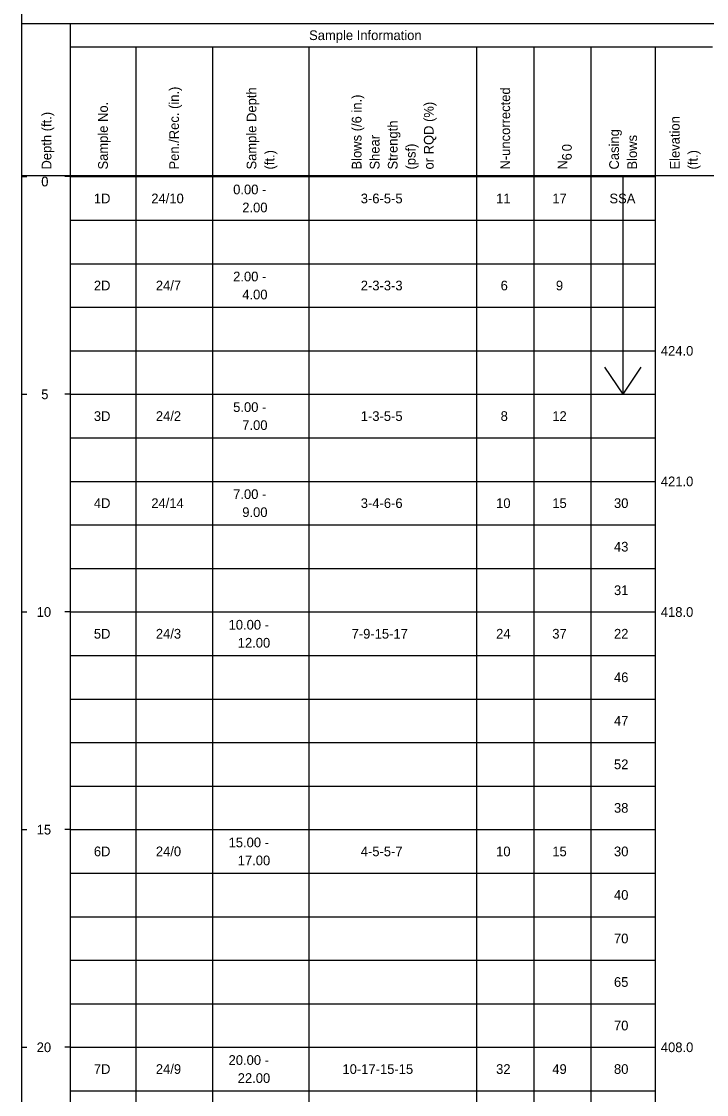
# Model space of a CAD drawing. Extents: x 9419 to 9552, y 6780 to 6865.
# Drawn here: x 9460.28 to 9476.01, y 6825.93 to 6850.58 of the extents above; entities that cross this region are included whole.
import ezdxf

# ---------------------------------------------------------------- set-up
doc = ezdxf.new("R2010")
doc.units = 0
doc.layers.add('7', color=7, linetype='Continuous')

msp = doc.modelspace()

# ---------------------------------------------------------------- linework, layer by layer
at = {"layer": '7'}
for q in [(9474.097, 6847.011), (9473.68, 6842.636), (9474.514, 6842.636)]:
    msp.add_line((9474.097, 6842.011), q, dxfattribs=at)
for points in [[(9460.282, 6860.114), (9460.282, 6821.983)], [(9460.282, 6850.528), (9491.778, 6850.528)], [(9461.4, 6850.528), (9461.4, 6821.983)], [(9461.4, 6849.992), (9476.148, 6849.992)], [(9462.909, 6849.992), (9462.909, 6821.983)], [(9464.665, 6849.992), (9464.665, 6821.983)], [(9466.879, 6849.992), (9466.879, 6821.983)], [(9470.734, 6849.992), (9470.734, 6821.983)], [(9472.046, 6849.992), (9472.046, 6821.983)], [(9473.359, 6849.992), (9473.359, 6821.983)], [(9474.835, 6849.992), (9474.835, 6821.983)], [(9460.282, 6847.038), (9491.778, 6847.038)], [(9460.282, 6847.011), (9460.404, 6847.011)], [(9461.4, 6847.011), (9461.279, 6847.011)], [(9461.4, 6847.011), (9462.909, 6847.011)], [(9462.909, 6847.011), (9464.665, 6847.011)], [(9464.665, 6847.011), (9466.879, 6847.011)], [(9466.879, 6847.011), (9470.734, 6847.011)], [(9470.734, 6847.011), (9472.046, 6847.011)], [(9472.046, 6847.011), (9473.359, 6847.011)], [(9473.359, 6847.011), (9474.835, 6847.011)], [(9461.4, 6846.011), (9462.909, 6846.011)], [(9462.909, 6846.011), (9464.665, 6846.011)], [(9464.665, 6846.011), (9466.879, 6846.011)], [(9466.879, 6846.011), (9470.734, 6846.011)], [(9470.734, 6846.011), (9472.046, 6846.011)], [(9472.046, 6846.011), (9473.359, 6846.011)], [(9473.359, 6846.011), (9474.835, 6846.011)], [(9461.4, 6845.011), (9462.909, 6845.011)], [(9462.909, 6845.011), (9464.665, 6845.011)], [(9464.665, 6845.011), (9466.879, 6845.011)], [(9466.879, 6845.011), (9470.734, 6845.011)], [(9470.734, 6845.011), (9472.046, 6845.011)], [(9472.046, 6845.011), (9473.359, 6845.011)], [(9473.359, 6845.011), (9474.835, 6845.011)], [(9461.4, 6844.011), (9462.909, 6844.011)], [(9462.909, 6844.011), (9464.665, 6844.011)], [(9464.665, 6844.011), (9466.879, 6844.011)], [(9466.879, 6844.011), (9470.734, 6844.011)], [(9470.734, 6844.011), (9472.046, 6844.011)], [(9472.046, 6844.011), (9473.359, 6844.011)], [(9473.359, 6844.011), (9474.835, 6844.011)], [(9461.4, 6843.011), (9462.909, 6843.011)], [(9462.909, 6843.011), (9464.665, 6843.011)], [(9464.665, 6843.011), (9466.879, 6843.011)], [(9466.879, 6843.011), (9470.734, 6843.011)], [(9470.734, 6843.011), (9472.046, 6843.011)], [(9472.046, 6843.011), (9473.359, 6843.011)], [(9473.359, 6843.011), (9474.835, 6843.011)], [(9460.282, 6842.011), (9460.404, 6842.011)], [(9461.4, 6842.011), (9461.279, 6842.011)], [(9461.4, 6842.011), (9462.909, 6842.011)], [(9462.909, 6842.011), (9464.665, 6842.011)], [(9464.665, 6842.011), (9466.879, 6842.011)], [(9466.879, 6842.011), (9470.734, 6842.011)], [(9470.734, 6842.011), (9472.046, 6842.011)], [(9472.046, 6842.011), (9473.359, 6842.011)], [(9473.359, 6842.011), (9474.835, 6842.011)], [(9461.4, 6841.011), (9462.909, 6841.011)], [(9462.909, 6841.011), (9464.665, 6841.011)], [(9464.665, 6841.011), (9466.879, 6841.011)], [(9466.879, 6841.011), (9470.734, 6841.011)], [(9470.734, 6841.011), (9472.046, 6841.011)], [(9472.046, 6841.011), (9473.359, 6841.011)], [(9473.359, 6841.011), (9474.835, 6841.011)], [(9461.4, 6840.011), (9462.909, 6840.011)], [(9462.909, 6840.011), (9464.665, 6840.011)], [(9464.665, 6840.011), (9466.879, 6840.011)], [(9466.879, 6840.011), (9470.734, 6840.011)], [(9470.734, 6840.011), (9472.046, 6840.011)], [(9472.046, 6840.011), (9473.359, 6840.011)], [(9473.359, 6840.011), (9474.835, 6840.011)], [(9461.4, 6839.011), (9462.909, 6839.011)], [(9462.909, 6839.011), (9464.665, 6839.011)], [(9464.665, 6839.011), (9466.879, 6839.011)], [(9466.879, 6839.011), (9470.734, 6839.011)], [(9470.734, 6839.011), (9472.046, 6839.011)], [(9472.046, 6839.011), (9473.359, 6839.011)], [(9473.359, 6839.011), (9474.835, 6839.011)], [(9461.4, 6838.011), (9462.909, 6838.011)], [(9462.909, 6838.011), (9464.665, 6838.011)], [(9464.665, 6838.011), (9466.879, 6838.011)], [(9466.879, 6838.011), (9470.734, 6838.011)], [(9470.734, 6838.011), (9472.046, 6838.011)], [(9472.046, 6838.011), (9473.359, 6838.011)], [(9473.359, 6838.011), (9474.835, 6838.011)], [(9460.282, 6837.011), (9460.404, 6837.011)], [(9461.4, 6837.011), (9461.279, 6837.011)], [(9461.4, 6837.011), (9462.909, 6837.011)], [(9462.909, 6837.011), (9464.665, 6837.011)], [(9464.665, 6837.011), (9466.879, 6837.011)], [(9466.879, 6837.011), (9470.734, 6837.011)], [(9470.734, 6837.011), (9472.046, 6837.011)], [(9472.046, 6837.011), (9473.359, 6837.011)], [(9473.359, 6837.011), (9474.835, 6837.011)], [(9461.4, 6836.011), (9462.909, 6836.011)], [(9462.909, 6836.011), (9464.665, 6836.011)], [(9464.665, 6836.011), (9466.879, 6836.011)], [(9466.879, 6836.011), (9470.734, 6836.011)], [(9470.734, 6836.011), (9472.046, 6836.011)], [(9472.046, 6836.011), (9473.359, 6836.011)], [(9473.359, 6836.011), (9474.835, 6836.011)], [(9461.4, 6835.011), (9462.909, 6835.011)], [(9462.909, 6835.011), (9464.665, 6835.011)], [(9464.665, 6835.011), (9466.879, 6835.011)], [(9466.879, 6835.011), (9470.734, 6835.011)], [(9470.734, 6835.011), (9472.046, 6835.011)], [(9472.046, 6835.011), (9473.359, 6835.011)], [(9473.359, 6835.011), (9474.835, 6835.011)], [(9461.4, 6834.011), (9462.909, 6834.011)], [(9462.909, 6834.011), (9464.665, 6834.011)], [(9464.665, 6834.011), (9466.879, 6834.011)], [(9466.879, 6834.011), (9470.734, 6834.011)], [(9470.734, 6834.011), (9472.046, 6834.011)], [(9472.046, 6834.011), (9473.359, 6834.011)], [(9473.359, 6834.011), (9474.835, 6834.011)], [(9461.4, 6833.011), (9462.909, 6833.011)], [(9462.909, 6833.011), (9464.665, 6833.011)], [(9464.665, 6833.011), (9466.879, 6833.011)], [(9466.879, 6833.011), (9470.734, 6833.011)], [(9470.734, 6833.011), (9472.046, 6833.011)], [(9472.046, 6833.011), (9473.359, 6833.011)], [(9473.359, 6833.011), (9474.835, 6833.011)], [(9460.282, 6832.011), (9460.404, 6832.011)], [(9461.4, 6832.011), (9461.279, 6832.011)], [(9461.4, 6832.011), (9462.909, 6832.011)], [(9462.909, 6832.011), (9464.665, 6832.011)], [(9464.665, 6832.011), (9466.879, 6832.011)], [(9466.879, 6832.011), (9470.734, 6832.011)], [(9470.734, 6832.011), (9472.046, 6832.011)], [(9472.046, 6832.011), (9473.359, 6832.011)], [(9473.359, 6832.011), (9474.835, 6832.011)], [(9461.4, 6831.011), (9462.909, 6831.011)], [(9462.909, 6831.011), (9464.665, 6831.011)], [(9464.665, 6831.011), (9466.879, 6831.011)], [(9466.879, 6831.011), (9470.734, 6831.011)], [(9470.734, 6831.011), (9472.046, 6831.011)], [(9472.046, 6831.011), (9473.359, 6831.011)], [(9473.359, 6831.011), (9474.835, 6831.011)], [(9461.4, 6830.011), (9462.909, 6830.011)], [(9462.909, 6830.011), (9464.665, 6830.011)], [(9464.665, 6830.011), (9466.879, 6830.011)], [(9466.879, 6830.011), (9470.734, 6830.011)], [(9470.734, 6830.011), (9472.046, 6830.011)], [(9472.046, 6830.011), (9473.359, 6830.011)], [(9473.359, 6830.011), (9474.835, 6830.011)], [(9461.4, 6829.011), (9462.909, 6829.011)], [(9462.909, 6829.011), (9464.665, 6829.011)], [(9464.665, 6829.011), (9466.879, 6829.011)], [(9466.879, 6829.011), (9470.734, 6829.011)], [(9470.734, 6829.011), (9472.046, 6829.011)], [(9472.046, 6829.011), (9473.359, 6829.011)], [(9473.359, 6829.011), (9474.835, 6829.011)], [(9461.4, 6828.011), (9462.909, 6828.011)], [(9462.909, 6828.011), (9464.665, 6828.011)], [(9464.665, 6828.011), (9466.879, 6828.011)], [(9466.879, 6828.011), (9470.734, 6828.011)], [(9470.734, 6828.011), (9472.046, 6828.011)], [(9472.046, 6828.011), (9473.359, 6828.011)], [(9473.359, 6828.011), (9474.835, 6828.011)], [(9460.282, 6827.011), (9460.404, 6827.011)], [(9461.4, 6827.011), (9461.279, 6827.011)], [(9461.4, 6827.011), (9462.909, 6827.011)], [(9462.909, 6827.011), (9464.665, 6827.011)], [(9464.665, 6827.011), (9466.879, 6827.011)], [(9466.879, 6827.011), (9470.734, 6827.011)], [(9470.734, 6827.011), (9472.046, 6827.011)], [(9472.046, 6827.011), (9473.359, 6827.011)], [(9473.359, 6827.011), (9474.835, 6827.011)], [(9461.4, 6826.011), (9462.909, 6826.011)], [(9462.909, 6826.011), (9464.665, 6826.011)], [(9464.665, 6826.011), (9466.879, 6826.011)], [(9466.879, 6826.011), (9470.734, 6826.011)], [(9470.734, 6826.011), (9472.046, 6826.011)], [(9472.046, 6826.011), (9473.359, 6826.011)], [(9473.359, 6826.011), (9474.835, 6826.011)]]:
    msp.add_lwpolyline(points, dxfattribs=at)

# ---------------------------------------------------------------- texts
for s, height, p in [('Sample Information', 0.2228, (9466.887, 6850.149)), ('0', 0.223, (9460.736, 6846.788)), ('0.00 -', 0.2228, (9465.143, 6846.606)), ('1D', 0.2228, (9461.945, 6846.399)), ('24/10', 0.2228, (9463.263, 6846.399)), ('2.00', 0.2228, (9465.352, 6846.192)), ('3-6-5-5', 0.2228, (9468.073, 6846.399)), ('11', 0.2228, (9471.181, 6846.399)), (' 17', 0.2228, (9472.388, 6846.399)), ('SSA', 0.2228, (9473.783, 6846.399)), ('2.00 -', 0.2228, (9465.143, 6844.606)), ('2D', 0.2228, (9461.945, 6844.399)), ('24/7', 0.2228, (9463.368, 6844.399)), ('2-3-3-3', 0.2228, (9468.073, 6844.399)), ('6', 0.223, (9471.285, 6844.399)), ('  9', 0.2228, (9472.388, 6844.399)), ('4.00', 0.2228, (9465.352, 6844.192)), ('424.0', 0.2228, (9474.963, 6842.899)), ('5', 0.223, (9460.736, 6841.899)), ('5.00 -', 0.2228, (9465.143, 6841.606)), ('3D', 0.2228, (9461.945, 6841.399)), ('24/2', 0.2228, (9463.368, 6841.399)), ('1-3-5-5', 0.2228, (9468.073, 6841.399)), ('8', 0.223, (9471.285, 6841.399)), (' 12', 0.2228, (9472.388, 6841.399)), ('7.00', 0.2228, (9465.352, 6841.192)), ('421.0', 0.2228, (9474.963, 6839.899)), ('7.00 -', 0.2228, (9465.143, 6839.606)), ('4D', 0.2228, (9461.945, 6839.399)), ('24/14', 0.2228, (9463.263, 6839.399)), ('3-4-6-6', 0.2228, (9468.073, 6839.399)), ('10', 0.2228, (9471.181, 6839.399)), (' 15', 0.2228, (9472.388, 6839.399)), ('30', 0.2228, (9473.887, 6839.399)), ('9.00', 0.2228, (9465.352, 6839.192)), ('43', 0.2228, (9473.887, 6838.399)), ('31', 0.2228, (9473.887, 6837.399)), ('10', 0.2228, (9460.632, 6836.899)), ('418.0', 0.2228, (9474.963, 6836.899)), ('10.00 -', 0.2228, (9465.038, 6836.606)), ('5D', 0.2228, (9461.945, 6836.399)), ('24/3', 0.2228, (9463.368, 6836.399)), ('7-9-15-17', 0.2228, (9467.863, 6836.399)), ('24', 0.2228, (9471.181, 6836.399)), (' 37', 0.2228, (9472.388, 6836.399)), ('22', 0.2228, (9473.887, 6836.399)), ('12.00', 0.2228, (9465.248, 6836.192)), ('46', 0.2228, (9473.887, 6835.399)), ('47', 0.2228, (9473.887, 6834.399)), ('52', 0.2228, (9473.887, 6833.399)), ('38', 0.2228, (9473.887, 6832.399)), ('15', 0.2228, (9460.632, 6831.899)), ('6D', 0.2228, (9461.945, 6831.399)), ('24/0', 0.2228, (9463.368, 6831.399)), ('15.00 -', 0.2228, (9465.038, 6831.606)), ('4-5-5-7', 0.2228, (9468.073, 6831.399)), ('10', 0.2228, (9471.181, 6831.399)), (' 15', 0.2228, (9472.388, 6831.399)), ('30', 0.2228, (9473.887, 6831.399)), ('17.00', 0.2228, (9465.248, 6831.192)), ('40', 0.2228, (9473.887, 6830.399)), ('70', 0.2228, (9473.887, 6829.399)), ('65', 0.2228, (9473.887, 6828.399)), ('70', 0.2228, (9473.887, 6827.399)), ('20', 0.2228, (9460.632, 6826.899)), ('408.0', 0.2228, (9474.963, 6826.899)), ('20.00 -', 0.2228, (9465.038, 6826.606)), ('7D', 0.2228, (9461.945, 6826.399)), ('24/9', 0.2228, (9463.368, 6826.399)), ('10-17-15-15', 0.2228, (9467.653, 6826.399)), ('32', 0.2228, (9471.181, 6826.399)), (' 49', 0.2228, (9472.388, 6826.399)), ('80', 0.2228, (9473.887, 6826.399)), ('22.00', 0.2228, (9465.248, 6826.192))]:
    msp.add_text(s, height=height, dxfattribs=at).set_placement(p)
for s, height, p in [('Pen./Rec. (in.)', 0.2228, (9463.898, 6847.175)), ('Sample Depth', 0.2228, (9465.676, 6847.175)), ('Blows (/6 in.)', 0.2228, (9468.09, 6847.175)), ('N-uncorrected', 0.2228, (9471.502, 6847.175)), ('Sample No.', 0.2228, (9462.266, 6847.175)), ('or RQD (%%%)', 0.2228, (9469.746, 6847.175)), ('Depth (ft.)', 0.2228, (9460.97, 6847.175)), ('Elevation', 0.2228, (9475.396, 6847.175)), ('Strength', 0.2228, (9468.918, 6847.175)), ('Shear', 0.2228, (9468.504, 6847.175)), ('Casing ', 0.2228, (9474.001, 6847.175)), ('Blows', 0.2228, (9474.416, 6847.175)), ('(psf)', 0.2228, (9469.332, 6847.175)), ('0', 0.223, (9472.918, 6847.594)), ('(ft.)', 0.2228, (9466.09, 6847.175)), ('6', 0.223, (9472.918, 6847.384)), ('(ft.)', 0.2228, (9475.81, 6847.175)), ('N', 0.223, (9472.814, 6847.175))]:
    msp.add_text(s, height=height, rotation=90, dxfattribs=at).set_placement(p)

doc.saveas('drawing.dxf')
